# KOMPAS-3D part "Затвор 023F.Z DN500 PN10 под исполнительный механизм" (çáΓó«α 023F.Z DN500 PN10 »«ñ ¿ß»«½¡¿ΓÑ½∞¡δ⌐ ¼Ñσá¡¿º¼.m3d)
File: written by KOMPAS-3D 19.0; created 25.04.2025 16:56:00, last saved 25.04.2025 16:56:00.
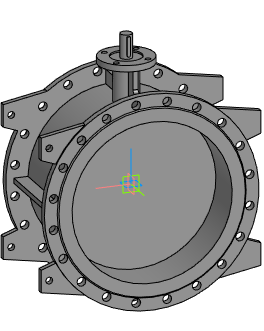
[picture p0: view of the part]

Document properties: Автор: Евгений; Полное имя файла: E:\Dendor Работа Сачек\3D для проекитирвщиков\1.7 Тип 023F.Z Затвор дисковый поворотный фланцевый с двумя эксцентриками\stp_Тип 023F.Z. Затвор под исполн. механизм\Затвор 023F.Z DN500 PN10 под исполнительный механизм.m3d

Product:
- Part/product: Затвор 023F.Z DN500 PN10 под исполнительный механизм

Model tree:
1. Операция без истории:1  (labels: Затвор 023F.Z DN500 PN10 под исполнительный механизм)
